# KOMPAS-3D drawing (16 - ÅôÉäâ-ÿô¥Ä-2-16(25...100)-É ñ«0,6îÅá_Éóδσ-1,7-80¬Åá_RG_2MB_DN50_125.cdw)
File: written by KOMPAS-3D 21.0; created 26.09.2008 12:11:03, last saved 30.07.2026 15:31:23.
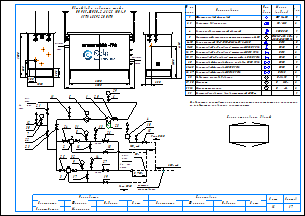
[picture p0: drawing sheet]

Sheets 1-2: A3, landscape

Document properties: Наименование: Макро:21; Автор: RaskoAdmin; Форматы листов документа: 2xA3; Полное имя файла: \\ur38nt01\Departments\КТО\КБ ПУРДГ\Заявки\Прайс-лист на типовые шкафы ГРПШ\ПУРДГ_стандарт_30_04_2026\ПУРДГ с RG_2MB\ПУРДГ-ШУЭО-2-16(25...100)-Р до0,6МПа_Рвых-1,7-80кПа_RG_2MB_DN50_125.cdw

Title block, sheet 1: Наименование: Пункт учета газа / ПУГ-Ш-400-Р / ЛГТИ.485922.001ТУ; designation: ЛГТИ.03.4411141; sheet number: 1; Количество листов документа: 2; organisation: ООО "ЭЛЬСТЕР Газэлектроника"; Форматы листов документа: A3; stored path: C:\Рабочие документы\Компас\ПУГ\Схема.cdw; Разработал: Устинов; Проверил: Кошкин; Утвердил: Кошкин
Title block, sheet 2: sheet number: 2; stored path: D:\Рабочие документы\Заявки\ПУРДГ\ПУРДГ-ШУЭО-2-100-Р 4411220.cdw; designation, second copy: ЛГТИ.03.4411141-

Views: Вид 1, Вид 2
Referenced files: wcvoit.frw
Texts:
  Normal
  № на
  схеме
  Усл.
  обозн.
  Марка
  (модель)
  Кол.
  Фильтр газовый фланцевый
  ФГ 16-50
  Регулятор давления газа
  RG/2MB
  Клапан предохранительный сбросной
  КПС DN20
  Измерительный комплекс с ротационным счетчиком Ду50
  СГ-ЭК-Р-(0,2...2,0)-
  Кран кнопочный VE-РАСКО-НЗ-1,6-G1/2-М20
  DN15
  Кран шаровой "под приварку" штуцерный DN20 PN16
  DN20
  Кран шаровой "под приварку" штуцерный DN15 PN16
  Кран шаровой "под приварку" штуцерный п/п DN20 PN16
  Кран шаровой фланцевый с мех. приводом DN50 PN16
  Кран шаровой фланцевый DN50 PN16
  Кран шаровой фланцевый DN125 PN16
  DN50
  DN125
  Индикатор перепада давления
  Манометр
  Манометр-напоромер
  Электрообогреватель взрывозащищенный 400Вт
  Delta 15
  0...     МПа
  0...     кПа
  Общий вид и габариты шкафа
  ПУРДГ-ШУЭО-2-16(25...100)-Р
  Выход газа
  Вход газа
  logo-rasko-ge.png
  DN 1
  местное
  сопротивление
  Римп DN20
  Выход
  газа
  Р=     кПа
  Вход
  Р=       МПа
  PDI
  Схема открывания дверей
  Предприятие изготовитель может заменять комплектующие на аналогичные,
  не ухудшающие заявленных характеристик.
  Должность
  Конструктор
  Фамилия
  Подпись
  Дата
  Согласовано
  Максимкин
  Лист
  Листов
  POLYLINE_STYLE_0.18_RGB_0_0_0
  POLYLINE_STYLE_0.50_RGB_0_0_0
  POLYLINE_STYLE_0.34_RGB_0_0_0
  PHANTOM_RGB_0_0_0_SC_1_THICK_0.18
  K5LT_THIN_RGB_0_0_0_THICK_0.18
  K5LT32769_RGB_0_0_0_THICK_0.18
  K5LT12_RGB_0_0_0_SC_1_THICK_0.18
  K5LT_DASHED_RGB_0_0_0_SC_1_THICK_0.18
  ACISOTGL_RGB_0_0_0_SC_0.8_THICK_0.25
  CONTINUOUS_RGB_0_127_31_THICK_0.3
  CONTINUOUS_RGB_0_0_255_THICK_0.35
  CONTINUOUS_RGB_255_0_0_THICK_0.35
  POLYLINE_STYLE_0.25_RGB_0_0_0
  CONTINUOUS_RGB_0_0_0_THICK_0.5
  POLYLINE_STYLE_0.35_RGB_0_0_255
  CONTINUOUS_RGB_0_0_0_THICK_0.4
  CONTINUOUS_RGB_0_0_0_THICK_0.35
  НЕВИДИМАЯ_RGB_0_0_0_SC_0.3_THICK_0.25
  СONTINUOUS_RGB_0_0_0_THICK_0.25
  ОСЕВАЯ2_RGB_248_153_30_SC_0.3_THICK_0.25
  Без оформления
Dimensions and other numbers on the sheet: 1; 2, 3; 2; 4; 5; 6-10; 11-15; 16, 17; 18, 19; 20; 21-25; 26, 27; 28; 29, 30; 31, 32; 33; 1500; 250; 300; 1050; 550; 305; 2500; 4130; 2000; 2800; 5,,,7DN 1; 7; 30; 12; 21; 22; 23; 11; 6; 29; 24; 31; 8; 16; 13; 26; 18; 10; 15; 25; 32; 9; 3; 17; 14; 27; 19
